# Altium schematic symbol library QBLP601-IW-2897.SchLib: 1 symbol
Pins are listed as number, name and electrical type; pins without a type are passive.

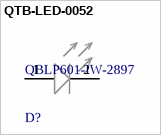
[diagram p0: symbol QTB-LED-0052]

## QTB-LED-0052
designator D?, comment QBLP601-IW-2897
LED WHITE DIFFUSED 0603 SMD; Manufacturer: QT Brightek (QTB); Lens Size: 0.8mm; Luminous Intensity: 900mcd; Test Current: 20mA; Lens Color: Yellow; Lens Style: Flat; Forward Voltage: 3.0V
footprint FP-QBLP601-IW-2897-MFG
pins: 1 ANODE (+), 2 CATHODE (-)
